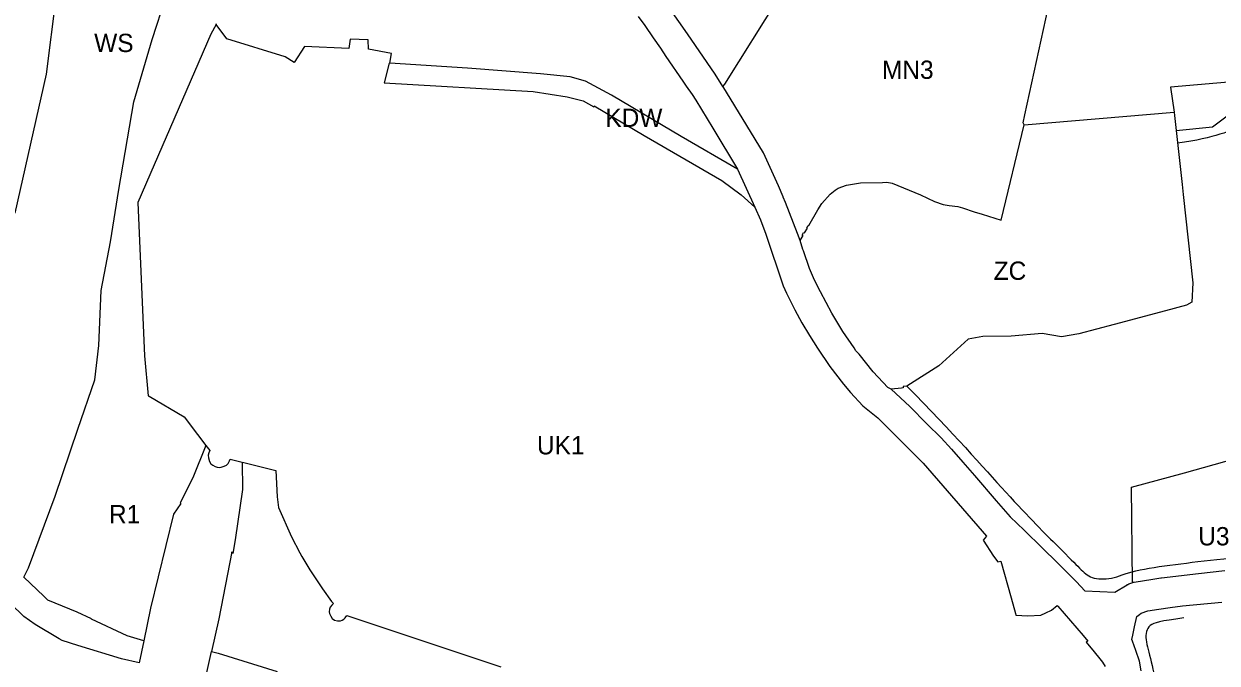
# Model space of a CAD drawing. Extents: x 7413438 to 7416393, y 5541665 to 5544118.
# Drawn here: x 7414051.4 to 7414442.9, y 5543072.4 to 5543282 of the extents above; entities that cross this region are included whole.
import ezdxf

# ---------------------------------------------------------------- set-up
doc = ezdxf.new("R2010")
doc.units = 0
for name, color, linetype in [('linie_rozgraniczajace', 7, 'Continuous'), ('linie_zabudowy_nieprzekraczalne', 7, 'Continuous'), ('oznaczenia_przeznaczen', 7, 'Continuous')]:
    doc.layers.add(name, color=color, linetype=linetype)

msp = doc.modelspace()

# ---------------------------------------------------------------- linework, layer by layer
at = {"layer": 'linie_rozgraniczajace'}
for p, q in [((7414058.82, 5543265.55), (7414071.65, 5543368.72)), ((7414093.48, 5543276.85), (7414102.25, 5543303.94)), ((7414299.53, 5543291.36), (7414281.28, 5543262.26)), ((7414379.75, 5543252.21), (7414388.93, 5543294.07)), ((7414252.91, 5543284.38), (7414255.07, 5543281.52)), ((7414269.13, 5543278.72), (7414263.45, 5543286.83)), ((7414114.44, 5543281.83), (7414112.72, 5543278.61)), ((7414114.44, 5543281.83), (7414114.62, 5543282.17)), ((7414117.94, 5543277.15), (7414114.44, 5543281.83)), ((7414255.07, 5543281.52), (7414257.89, 5543277.47)), ((7414087.49, 5543256.4), (7414093.48, 5543276.85)), ((7414112.72, 5543278.61), (7414088.8, 5543223.45)), ((7414137.11, 5543271.18), (7414117.94, 5543277.15)), ((7414158.46, 5543276.95), (7414158.05, 5543273.88)), ((7414164.29, 5543276.78), (7414158.46, 5543276.95)), ((7414164.41, 5543273.74), (7414164.29, 5543276.78)), ((7414257.89, 5543277.47), (7414260.21, 5543274.04)), ((7414278.16, 5543265.47), (7414269.13, 5543278.72)), ((7414143.46, 5543274.62), (7414140.1, 5543269.32)), ((7414158.05, 5543273.88), (7414143.46, 5543274.62)), ((7414172.02, 5543272.33), (7414164.41, 5543273.74)), ((7414171.41, 5543269.11), (7414172.02, 5543272.33)), ((7414260.21, 5543274.04), (7414261.99, 5543271.26)), ((7414261.99, 5543271.26), (7414267.59, 5543263.25)), ((7414140.1, 5543269.32), (7414137.11, 5543271.18)), ((7414171.22, 5543269.12), (7414169.63, 5543262.7)), ((7414171.41, 5543269.11), (7414171.22, 5543269.12)), ((7414196.97, 5543267.52), (7414171.41, 5543269.11)), ((7414220.88, 5543265.58), (7414196.97, 5543267.52)), ((7414511.08, 5543268.54), (7414427.62, 5543261.29)), ((7414048.51, 5543220), (7414058.82, 5543265.55)), ((7414230.58, 5543264.65), (7414220.88, 5543265.58)), ((7414235.67, 5543263.26), (7414230.58, 5543264.65)), ((7414280.71, 5543261.5), (7414278.16, 5543265.47)), ((7414169.63, 5543262.7), (7414218.47, 5543259.79)), ((7414218.47, 5543259.79), (7414229.66, 5543258.12)), ((7414244.2, 5543258.58), (7414235.67, 5543263.26)), ((7414267.59, 5543263.25), (7414268.73, 5543261.54)), ((7414268.73, 5543261.54), (7414270.66, 5543258.88)), ((7414280.74, 5543261.55), (7414280.71, 5543261.5)), ((7414281.28, 5543262.26), (7414280.74, 5543261.55)), ((7414288.58, 5543248.67), (7414280.74, 5543261.55)), ((7414427.62, 5543261.29), (7414428.78, 5543253.05)), ((7414082.58, 5543227.75), (7414087.49, 5543256.4)), ((7414229.66, 5543258.12), (7414234.88, 5543256.74)), ((7414234.88, 5543256.74), (7414238.4, 5543254.82)), ((7414266.99, 5543245.07), (7414244.2, 5543258.58)), ((7414270.66, 5543258.88), (7414271.8, 5543257.04)), ((7414271.8, 5543257.04), (7414277.42, 5543247.77)), ((7414238.4, 5543254.82), (7414238.46, 5543255.17)), ((7414238.46, 5543255.17), (7414254.88, 5543245.38)), ((7414379.21, 5543249.61), (7414379.78, 5543252.2)), ((7414379.58, 5543248.94), (7414428.78, 5543253.05)), ((7414379.78, 5543252.2), (7414379.75, 5543252.21)), ((7414428.78, 5543253.05), (7414428.78, 5543253.04)), ((7414428.78, 5543253.05), (7414428.78, 5543253.04)), ((7414428.78, 5543253.04), (7414428.9, 5543251.98)), ((7414428.9, 5543251.98), (7414429.45, 5543247.01)), ((7414441.38, 5543248.29), (7414448.36, 5543253.51)), ((7414277.42, 5543247.77), (7414285.57, 5543234.42)), ((7414294, 5543239.78), (7414288.58, 5543248.67)), ((7414372.04, 5543217.62), (7414379.58, 5543248.94)), ((7414379.58, 5543248.94), (7414379.21, 5543249.61)), ((7414429.45, 5543247.01), (7414441.38, 5543248.29)), ((7414254.88, 5543245.38), (7414280.42, 5543230.66)), ((7414285.57, 5543234.42), (7414266.99, 5543245.07)), ((7414429.45, 5543247.01), (7414431.41, 5543229.3)), ((7414298.95, 5543228.92), (7414294, 5543239.78)), ((7414285.57, 5543234.42), (7414291.19, 5543221.87)), ((7414280.42, 5543230.66), (7414286.7, 5543226.01)), ((7414300.45, 5543225.3), (7414298.95, 5543228.92)), ((7414317.53, 5543227.52), (7414318.56, 5543228.14)), ((7414318.56, 5543228.14), (7414321.31, 5543229.15)), ((7414321.31, 5543229.15), (7414325.83, 5543229.89)), ((7414325.83, 5543229.89), (7414333.04, 5543230.04)), ((7414333.04, 5543230.04), (7414334.54, 5543230.1)), ((7414334.54, 5543230.1), (7414336.27, 5543229.83)), ((7414336.27, 5543229.83), (7414345.57, 5543225.93)), ((7414431.41, 5543229.3), (7414431.76, 5543226.06)), ((7414079.86, 5543210.57), (7414082.58, 5543227.75)), ((7414286.7, 5543226.01), (7414291.19, 5543221.87)), ((7414300.52, 5543225.22), (7414300.45, 5543225.3)), ((7414301.23, 5543223.42), (7414300.52, 5543225.22)), ((7414313.24, 5543223.13), (7414315.96, 5543226.13)), ((7414315.96, 5543226.13), (7414317.53, 5543227.52)), ((7414345.57, 5543225.93), (7414350.16, 5543223.81)), ((7414431.76, 5543226.06), (7414434.96, 5543197.08)), ((7414088.8, 5543223.45), (7414090.95, 5543173.14)), ((7414291.19, 5543221.87), (7414293.03, 5543217.73)), ((7414305.25, 5543213.25), (7414301.23, 5543223.42)), ((7414308.92, 5543215.86), (7414311.92, 5543221.07)), ((7414311.92, 5543221.07), (7414313.24, 5543223.13)), ((7414350.16, 5543223.81), (7414352.95, 5543222.83)), ((7414352.95, 5543222.83), (7414354.91, 5543222.43)), ((7414354.91, 5543222.43), (7414357.79, 5543222.09)), ((7414357.79, 5543222.09), (7414359.32, 5543221.67)), ((7414359.32, 5543221.67), (7414363.2, 5543220.4)), ((7414363.2, 5543220.4), (7414365.74, 5543219.59)), ((7414293.03, 5543217.73), (7414294.78, 5543213.02)), ((7414365.74, 5543219.59), (7414372.04, 5543217.62)), ((7414294.78, 5543213.02), (7414300.49, 5543196.08)), ((7414306.13, 5543211.03), (7414305.25, 5543213.25)), ((7414306.13, 5543211.03), (7414307.01, 5543212.61)), ((7414306.7, 5543212.79), (7414307.17, 5543213.58)), ((7414307.01, 5543212.61), (7414306.7, 5543212.79)), ((7414307.17, 5543213.58), (7414307.52, 5543213.48)), ((7414307.52, 5543213.48), (7414308.47, 5543215)), ((7414308.21, 5543215.12), (7414308.65, 5543215.95)), ((7414308.47, 5543215), (7414308.21, 5543215.12)), ((7414308.65, 5543215.95), (7414308.92, 5543215.86)), ((7414076.72, 5543194.61), (7414079.86, 5543210.57)), ((7414306.96, 5543208.01), (7414306.13, 5543211.03)), ((7414307.18, 5543207.55), (7414306.96, 5543208.01)), ((7414309.11, 5543201.83), (7414307.18, 5543207.55)), ((7414310.76, 5543197.95), (7414309.11, 5543201.83)), ((7414312.7, 5543194.14), (7414310.76, 5543197.95)), ((7414434.96, 5543197.08), (7414434.56, 5543190.73)), ((7414075.93, 5543176.56), (7414076.72, 5543194.61)), ((7414300.49, 5543196.08), (7414301.64, 5543193.75)), ((7414301.64, 5543193.75), (7414304.34, 5543188.27)), ((7414316.49, 5543187.17), (7414312.7, 5543194.14)), ((7414432.87, 5543189.76), (7414425.91, 5543187.93)), ((7414434.56, 5543190.73), (7414432.87, 5543189.76)), ((7414304.34, 5543188.27), (7414306.66, 5543184.02)), ((7414320.11, 5543181.15), (7414316.49, 5543187.17)), ((7414425.91, 5543187.93), (7414409.08, 5543183.41)), ((7414306.66, 5543184.02), (7414309.14, 5543179.84)), ((7414323.8, 5543175.75), (7414320.11, 5543181.15)), ((7414409.08, 5543183.41), (7414397.5, 5543180.4)), ((7414309.14, 5543179.84), (7414311.71, 5543175.73)), ((7414361.21, 5543178.6), (7414351.53, 5543169.88)), ((7414366.06, 5543179.47), (7414361.21, 5543178.6)), ((7414375.27, 5543179.58), (7414366.06, 5543179.47)), ((7414385.45, 5543180.53), (7414375.27, 5543179.58)), ((7414391.86, 5543179.42), (7414385.45, 5543180.53)), ((7414397.5, 5543180.4), (7414391.86, 5543179.42)), ((7414074.68, 5543165.32), (7414075.93, 5543176.56)), ((7414311.71, 5543175.73), (7414315.84, 5543169.73)), ((7414324.31, 5543174.85), (7414323.8, 5543175.75)), ((7414325.44, 5543173.74), (7414324.31, 5543174.85)), ((7414330.08, 5543167.92), (7414325.44, 5543173.74)), ((7414090.95, 5543173.14), (7414092.17, 5543160.1)), ((7414315.84, 5543169.73), (7414320.26, 5543163.94)), ((7414351.53, 5543169.88), (7414341.12, 5543163.28)), ((7414334.85, 5543162.85), (7414330.08, 5543167.92)), ((7414069.08, 5543149.16), (7414074.68, 5543165.32)), ((7414320.26, 5543163.94), (7414322.55, 5543161.12)), ((7414335.76, 5543162.36), (7414334.85, 5543162.85)), ((7414335.89, 5543162.27), (7414335.76, 5543162.36)), ((7414335.94, 5543162.28), (7414335.89, 5543162.27)), ((7414339.34, 5543162.62), (7414335.94, 5543162.28)), ((7414335.94, 5543162.28), (7414342.04, 5543156.56)), ((7414339.87, 5543162.68), (7414339.34, 5543162.62)), ((7414339.91, 5543163.1), (7414339.87, 5543162.68)), ((7414341.12, 5543163.28), (7414339.91, 5543163.1)), ((7414092.17, 5543160.1), (7414092.51, 5543159.96)), ((7414092.51, 5543159.96), (7414103.99, 5543153.15)), ((7414322.55, 5543161.12), (7414326.65, 5543156.79)), ((7414326.65, 5543156.79), (7414331.58, 5543152.88)), ((7414342.04, 5543156.56), (7414347.68, 5543150.93)), ((7414103.99, 5543153.15), (7414108.38, 5543147.42)), ((7414331.58, 5543152.88), (7414346.44, 5543138.04)), ((7414347.68, 5543150.93), (7414352.38, 5543146.27)), ((7414061.63, 5543127.14), (7414069.08, 5543149.16)), ((7414108.38, 5543147.42), (7414111.08, 5543143.82)), ((7414352.38, 5543146.27), (7414355.75, 5543142.57)), ((7414111.08, 5543143.82), (7414106.86, 5543133.17)), ((7414111.08, 5543143.82), (7414111.54, 5543143.22)), ((7414111.54, 5543143.22), (7414112.35, 5543142.13)), ((7414112.35, 5543142.13), (7414112.08, 5543141.41)), ((7414355.75, 5543142.57), (7414359.43, 5543138.33)), ((7414112.08, 5543141.41), (7414111.85, 5543140.58)), ((7414111.85, 5543140.58), (7414111.94, 5543139.74)), ((7414111.94, 5543139.74), (7414112.32, 5543138.54)), ((7414112.32, 5543138.54), (7414112.73, 5543137.8)), ((7414118.41, 5543137.86), (7414118.87, 5543138.71)), ((7414118.87, 5543138.71), (7414119.1, 5543139.34)), ((7414119.1, 5543139.34), (7414123, 5543138.35)), ((7414123, 5543138.35), (7414123.16, 5543129.33)), ((7414123, 5543138.35), (7414123.59, 5543138.2)), ((7414123.59, 5543138.2), (7414134.02, 5543135.55)), ((7414359.43, 5543138.33), (7414363.24, 5543133.92)), ((7414432.13, 5543134.79), (7414452.48, 5543140.56)), ((7414112.73, 5543137.8), (7414113.35, 5543137.31)), ((7414113.35, 5543137.31), (7414114.15, 5543136.88)), ((7414114.15, 5543136.88), (7414114.81, 5543136.66)), ((7414114.81, 5543136.66), (7414115.49, 5543136.61)), ((7414115.49, 5543136.61), (7414116.1, 5543136.65)), ((7414116.1, 5543136.65), (7414117.05, 5543136.98)), ((7414117.05, 5543136.98), (7414117.89, 5543137.39)), ((7414117.89, 5543137.39), (7414118.41, 5543137.86)), ((7414134.02, 5543135.55), (7414134.48, 5543126.95)), ((7414346.44, 5543138.04), (7414367.24, 5543114.05)), ((7414414.83, 5543130.11), (7414432.13, 5543134.79)), ((7414432.13, 5543134.79), (7414432.13, 5543134.79)), ((7414106.86, 5543133.17), (7414102.62, 5543124.95)), ((7414363.24, 5543133.92), (7414370.41, 5543125.66)), ((7414052.91, 5543103.65), (7414061.63, 5543127.14)), ((7414123.16, 5543129.33), (7414120.66, 5543112.82)), ((7414134.48, 5543126.95), (7414134.94, 5543123.47)), ((7414415.09, 5543098.83), (7414414.83, 5543130.11)), ((7414414.83, 5543130.11), (7414414.83, 5543130.11)), ((7414102.91, 5543124.73), (7414100.45, 5543121.26)), ((7414102.62, 5543124.95), (7414102.62, 5543124.95)), ((7414102.62, 5543124.95), (7414102.91, 5543124.73)), ((7414134.94, 5543123.47), (7414139.2, 5543113.8)), ((7414370.41, 5543125.66), (7414375.02, 5543120.43)), ((7414100.45, 5543121.26), (7414092.96, 5543090.51)), ((7414375.02, 5543120.43), (7414379.55, 5543115.99)), ((7414379.55, 5543115.99), (7414385.53, 5543110.11)), ((7414120.66, 5543112.82), (7414119.96, 5543108.43)), ((7414139.2, 5543113.8), (7414141.93, 5543108.55)), ((7414367.24, 5543114.05), (7414366.09, 5543112.8)), ((7414366.09, 5543112.8), (7414369.55, 5543107.51)), ((7414119.56, 5543108.89), (7414115.35, 5543086.98)), ((7414119.66, 5543108.78), (7414119.56, 5543108.89)), ((7414119.96, 5543108.43), (7414119.66, 5543108.78)), ((7414141.93, 5543108.55), (7414142.58, 5543107.36)), ((7414142.58, 5543107.36), (7414145.23, 5543103.03)), ((7414369.55, 5543107.51), (7414370.88, 5543105.66)), ((7414385.53, 5543110.11), (7414390.35, 5543105.38)), ((7414051.39, 5543100.65), (7414052.91, 5543103.65)), ((7414145.23, 5543103.03), (7414149.36, 5543096.84)), ((7414370.88, 5543105.66), (7414371.87, 5543105.9)), ((7414371.87, 5543105.9), (7414371.88, 5543105.89)), ((7414371.88, 5543105.89), (7414375.32, 5543093.88)), ((7414390.35, 5543105.38), (7414396.78, 5543099.07)), ((7414057.93, 5543094.41), (7414051.39, 5543100.65)), ((7414396.78, 5543099.07), (7414399.47, 5543096.09)), ((7414421.81, 5543099.9), (7414415.62, 5543098.93)), ((7414424.43, 5543100.3), (7414421.81, 5543099.9)), ((7414424.66, 5543100.33), (7414424.43, 5543100.3)), ((7414436.75, 5543101.72), (7414424.66, 5543100.33)), ((7414445.41, 5543102.72), (7414436.75, 5543101.72)), ((7414149.36, 5543096.84), (7414152.31, 5543092.64)), ((7414399.47, 5543096.09), (7414409.31, 5543095.76)), ((7414409.31, 5543095.76), (7414413.34, 5543098.14)), ((7414413.34, 5543098.14), (7414413.4, 5543098.17)), ((7414413.4, 5543098.17), (7414413.53, 5543098.25)), ((7414413.53, 5543098.25), (7414413.88, 5543098.43)), ((7414413.88, 5543098.43), (7414414.24, 5543098.58)), ((7414414.24, 5543098.58), (7414414.61, 5543098.71)), ((7414414.61, 5543098.71), (7414414.99, 5543098.81)), ((7414414.99, 5543098.81), (7414415.09, 5543098.83)), ((7414415.38, 5543098.89), (7414415.09, 5543098.83)), ((7414415.48, 5543098.91), (7414415.38, 5543098.89)), ((7414415.62, 5543098.93), (7414415.48, 5543098.91)), ((7414051.4, 5543087.76), (7414047.02, 5543092)), ((7414059.22, 5543093.13), (7414057.93, 5543094.41)), ((7414068.84, 5543089.13), (7414059.22, 5543093.13)), ((7414152.37, 5543091.41), (7414151.89, 5543090.79)), ((7414152.31, 5543092.64), (7414153, 5543091.94)), ((7414153, 5543091.94), (7414152.37, 5543091.41)), ((7414375.32, 5543093.88), (7414376.75, 5543088.67)), ((7414388.58, 5543089.79), (7414390.39, 5543091.32)), ((7414390.39, 5543091.32), (7414390.59, 5543091.08)), ((7414427.43, 5543090.68), (7414431.53, 5543091.27)), ((7414431.53, 5543091.27), (7414444.41, 5543092.43)), ((7414055.07, 5543085.09), (7414051.4, 5543087.76)), ((7414073.56, 5543086.93), (7414068.84, 5543089.13)), ((7414092.96, 5543090.51), (7414090.71, 5543079.8)), ((7414151.64, 5543090.09), (7414151.6, 5543089.23)), ((7414151.6, 5543089.23), (7414151.65, 5543088.69)), ((7414151.89, 5543090.79), (7414151.64, 5543090.09)), ((7414151.65, 5543088.69), (7414152.06, 5543087.8)), ((7414152.06, 5543087.8), (7414152.57, 5543087.1)), ((7414156.4, 5543086.9), (7414156.84, 5543087.34)), ((7414156.84, 5543087.34), (7414157.31, 5543088.01)), ((7414157.31, 5543088.01), (7414207.82, 5543071.23)), ((7414376.75, 5543088.67), (7414376.88, 5543088.17)), ((7414376.88, 5543088.17), (7414380.75, 5543087.93)), ((7414380.75, 5543087.93), (7414385.09, 5543088.17)), ((7414385.09, 5543088.17), (7414386.63, 5543088.93)), ((7414386.63, 5543088.93), (7414388.58, 5543089.79)), ((7414390.59, 5543091.08), (7414398.88, 5543081.45)), ((7414415.81, 5543084.29), (7414416.52, 5543087.73)), ((7414416.52, 5543087.73), (7414417.45, 5543088.44)), ((7414417.45, 5543088.44), (7414417.99, 5543088.84)), ((7414417.99, 5543088.84), (7414420.15, 5543089.63)), ((7414420.15, 5543089.63), (7414423.71, 5543090.16)), ((7414423.71, 5543090.16), (7414427.43, 5543090.68)), ((7414062.97, 5543080.43), (7414055.07, 5543085.09)), ((7414073.54, 5543086.88), (7414073.56, 5543086.93)), ((7414085.24, 5543081.42), (7414073.54, 5543086.88)), ((7414115.35, 5543086.98), (7414112.92, 5543076.24)), ((7414152.57, 5543087.1), (7414153.27, 5543086.57)), ((7414153.27, 5543086.57), (7414154.31, 5543086.35)), ((7414154.31, 5543086.35), (7414155.22, 5543086.33)), ((7414155.22, 5543086.33), (7414155.84, 5543086.58)), ((7414155.84, 5543086.58), (7414156.4, 5543086.9)), ((7414415.46, 5543082.72), (7414415.81, 5543084.29)), ((7414063.91, 5543079.81), (7414062.97, 5543080.43)), ((7414069.05, 5543078.23), (7414063.91, 5543079.81)), ((7414090.71, 5543079.8), (7414085.24, 5543081.42)), ((7414090.71, 5543079.8), (7414089.19, 5543072.58)), ((7414398.88, 5543081.45), (7414400.42, 5543079.65)), ((7414400.42, 5543079.65), (7414399.95, 5543079.3)), ((7414414.89, 5543080.14), (7414415.22, 5543081.65)), ((7414415.09, 5543079.59), (7414414.89, 5543080.14)), ((7414416.24, 5543076.57), (7414415.09, 5543079.59)), ((7414415.22, 5543081.65), (7414415.46, 5543082.72)), ((7414069.04, 5543078.2), (7414069.05, 5543078.23)), ((7414083.47, 5543073.88), (7414069.04, 5543078.2)), ((7414111.14, 5543068.38), (7414112.92, 5543076.24)), ((7414112.92, 5543076.24), (7414115.08, 5543075.66)), ((7414115.08, 5543075.66), (7414134.44, 5543069.73)), ((7414399.95, 5543079.3), (7414401.98, 5543076.76)), ((7414401.98, 5543076.76), (7414402.06, 5543076.66)), ((7414402.06, 5543076.66), (7414404.8, 5543073.34)), ((7414417.38, 5543073.07), (7414416.24, 5543076.57)), ((7414089.19, 5543072.58), (7414083.47, 5543073.88)), ((7414404.8, 5543073.34), (7414405.28, 5543072.75)), ((7414405.28, 5543072.75), (7414406.15, 5543071.36)), ((7414417.91, 5543069.9), (7414417.38, 5543073.07))]:
    msp.add_line(p, q, dxfattribs=at)
at = {"layer": 'linie_zabudowy_nieprzekraczalne'}
for points in [[(7414687.23, 5543257.54), (7414640.54, 5543254.67), (7414631.57, 5543257.54), (7414619.22, 5543256.49), (7414614.66, 5543262.9), (7414609.18, 5543264.16), (7414546.97, 5543257.6), (7414481.96, 5543252.26), (7414449.78, 5543249.6), (7414442.77, 5543244.55), (7414429.85, 5543242.9)], [(7414341.07, 5543163.28), (7414356.51, 5543147.6), (7414375.53, 5543125.83), (7414392.4, 5543108.91), (7414398.25, 5543103.17), (7414401.25, 5543100.02), (7414408.23, 5543099.78), (7414415, 5543102.86), (7414429.11, 5543104.87), (7414443.72, 5543106.55), (7414466.68, 5543108.58), (7414484.3, 5543105.95), (7414507.74, 5543103.66), (7414536.5, 5543101.14), (7414544.43, 5543101.85), (7414560.45, 5543105.29), (7414569.76, 5543106.57), (7414580.19, 5543106.45), (7414585, 5543107.07), (7414589.21, 5543110.97), (7414589.59, 5543117.25), (7414589.25, 5543126.63), (7414589.81, 5543129.39), (7414593.09, 5543140.49), (7414594.13, 5543144.01), (7414594.78, 5543145.14), (7414596.31, 5543146.56), (7414597.95, 5543147.56), (7414603.22, 5543149.61), (7414607.81, 5543150.14), (7414636.45, 5543148.97), (7414652.66, 5543148.29), (7414679.53, 5543149.04), (7414698.29, 5543150.16)], [(7414431.95, 5543087.28), (7414424.23, 5543086.19), (7414420.06, 5543085.34), (7414419, 5543080.42), (7414421.28, 5543073.71), (7414423.39, 5543062.01), (7414425.39, 5543058.29), (7414430.81, 5543048.92), (7414433.87, 5543045.88), (7414444.69, 5543042.35), (7414474.63, 5543035.39), (7414481.89, 5543033.43), (7414483.16, 5543036.96), (7414485.08, 5543039.86), (7414490.96, 5543045.85), (7414497.7, 5543051.64), (7414500.63, 5543053.95), (7414503, 5543055.91), (7414505.09, 5543056.77), (7414509.77, 5543055.9), (7414530.22, 5543051.06), (7414537.37, 5543048.9), (7414539.27, 5543048.01), (7414540.33, 5543046.71), (7414543.6, 5543045.77), (7414547.8, 5543044.76), (7414549.47, 5543044.91), (7414562.64, 5543048.9), (7414579.93, 5543054.1), (7414600, 5543060.19), (7414616.25, 5543065.09), (7414646.94, 5543074.37), (7414667.99, 5543080.68), (7414683.48, 5543085.15), (7414703.27, 5543094.8), (7414711.92, 5543099.17), (7414719.64, 5543105.12), (7414735.49, 5543119.82), (7414750.36, 5543133.73), (7414756.76, 5543139.86), (7414758.13, 5543140.61), (7414759.94, 5543140.74), (7414761.63, 5543140.06), (7414763.36, 5543138.3), (7414765.4, 5543135.79), (7414765.75, 5543133.75), (7414763.94, 5543132.46), (7414737.28, 5543107.58), (7414725.35, 5543096.6), (7414718.45, 5543091.83), (7414705.59, 5543084.52), (7414694.22, 5543079.04), (7414682.4, 5543074.49), (7414654.76, 5543066.06), (7414598.61, 5543048.77), (7414574.71, 5543041.85)]]:
    msp.add_open_spline(points, degree=3, dxfattribs=at)

# ---------------------------------------------------------------- texts
at = {"layer": 'oznaczenia_przeznaczen'}
for s, p in [('WS', (7414074.45, 5543272.76)), ('MN3', (7414332.92, 5543263.97)), ('KDW', (7414242.16, 5543248.21)), ('ZC', (7414369.56, 5543198.09)), ('UK1', (7414219.73, 5543140.87)), ('R1', (7414079.31, 5543118.27)), ('U3', (7414436.68, 5543111.04))]:
    msp.add_text(s, height=6, dxfattribs=at).set_placement(p)

doc.saveas('drawing.dxf')
